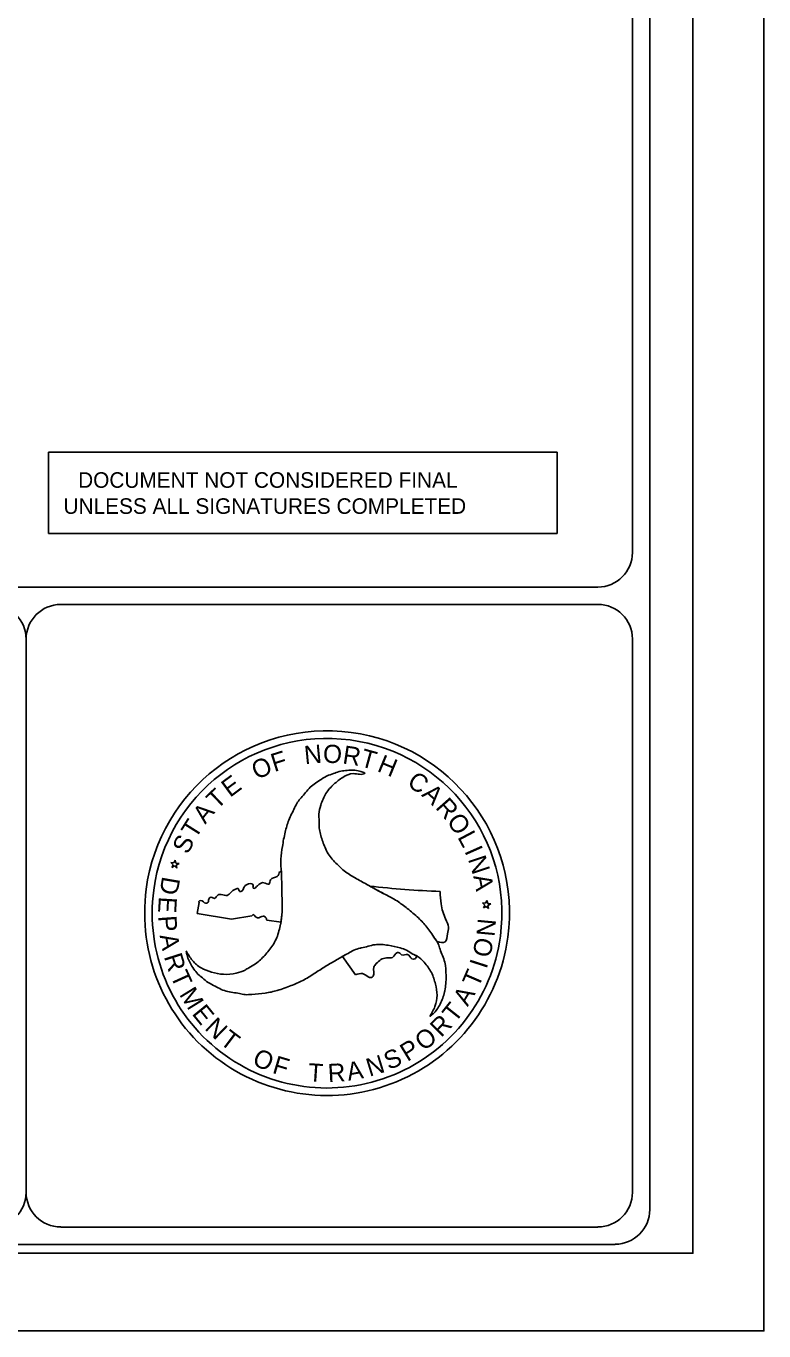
# Model space of a CAD drawing. Extents: x 2128934 to 2134034, y 641595 to 644895.
# Drawn here: x 2133394 to 2134034, y 641595 to 642727 of the extents above; entities that cross this region are included whole.
import ezdxf

# ---------------------------------------------------------------- set-up
doc = ezdxf.new("R2010")
doc.units = 0
for name, color, linetype in [('Sheet Plot Border Inside CELL', 7, 'Continuous'), ('Sheet Plot Border Outside CELL', 7, 'Continuous'), ('Sheet Sticker Exception Certification CELL', 7, 'Continuous'), ('Sheet Title CELL', 7, 'Continuous')]:
    doc.layers.add(name, color=color, linetype=linetype)

msp = doc.modelspace()

# ---------------------------------------------------------------- linework, layer by layer
at = {"layer": 'Sheet Plot Border Inside CELL'}
msp.add_lwpolyline([(2128972.8, 641662.5), (2133972.3, 641662.5), (2133972.3, 644827.8), (2128972.8, 644827.8)], close=True, dxfattribs=at)
at = {"layer": 'Sheet Plot Border Outside CELL'}
msp.add_lwpolyline([(2128933.8, 641595.1), (2134033.8, 641595.1), (2134033.8, 644895.1), (2128933.8, 644895.1)], close=True, dxfattribs=at)
at = {"layer": 'Sheet Sticker Exception Certification CELL'}
for p, q in [((2133413.5, 642286.9), (2133413.5, 642357.4)), ((2133413.5, 642357.4), (2133854.5, 642357.4)), ((2133854.5, 642357.4), (2133854.5, 642286.9)), ((2133854.5, 642286.9), (2133413.5, 642286.9))]:
    msp.add_line(p, q, dxfattribs=at)
at = {"layer": 'Sheet Title CELL'}
for p, q in [((2129629.8, 642240.2), (2133889.8, 642240.2)), ((2133424.1, 642225.2), (2133889.8, 642225.2)), ((2133394.1, 641715.2), (2133394.1, 642195.2)), ((2133688.1, 642079.3), (2133687.8, 642079)), ((2133688.1, 642079.3), (2133687.8, 642079)), ((2133521.5, 641999.5), (2133519.6, 642001.5)), ((2133519.6, 642001.5), (2133522.3, 642001.1)), ((2133520.4, 641997), (2133521.5, 641999.5)), ((2133522.7, 641998.4), (2133520.4, 641997)), ((2133522.3, 642001.1), (2133523.4, 642003.5)), ((2133524.7, 641996.5), (2133522.7, 641998.4)), ((2133523.4, 642003.5), (2133524, 642000.9)), ((2133524, 642000.9), (2133526.7, 642000.5)), ((2133526.7, 642000.5), (2133524.2, 641999.2)), ((2133524.2, 641999.2), (2133524.7, 641996.5)), ((2133692.1, 641980.8), (2133692.1, 641980.8)), ((2133542.5, 641957.3), (2133544.1, 641966.7)), ((2133792.5, 641966), (2133789.8, 641966.4)), ((2133789.8, 641966.4), (2133791.8, 641964.5)), ((2133791.8, 641964.5), (2133790.7, 641962)), ((2133790.7, 641962), (2133793, 641963.3)), ((2133793.7, 641968.4), (2133792.5, 641966)), ((2133793, 641963.3), (2133795, 641961.5)), ((2133794.3, 641965.8), (2133793.7, 641968.4)), ((2133796.9, 641965.6), (2133794.3, 641965.8)), ((2133794.5, 641964.2), (2133796.9, 641965.6)), ((2133795, 641961.5), (2133794.5, 641964.2)), ((2133572.1, 641952.2), (2133542.5, 641957.3)), ((2133589.9, 641955), (2133572.1, 641952.2)), ((2133615.1, 641949.5), (2133602.7, 641951.3)), ((2133811.7, 641936.5), (2133811.7, 641936.5)), ((2133679.6, 641903.9), (2133668.3, 641919.9)), ((2133668.3, 641919.9), (2133668.3, 641919.9))]:
    msp.add_line(p, q, dxfattribs=at)
for points in [[(2133934.8, 641700.2), (2133934.8, 644790.1)], [(2133919.8, 642270.1), (2133919.8, 644775.2)], [(2133919.8, 641715.2), (2133919.8, 642195.2)], [(2133424.1, 641685.2), (2133889.8, 641685.2)], [(2129464.8, 641670.1), (2133904.8, 641670.1)]]:
    msp.add_lwpolyline(points, dxfattribs=at)
for centre, radius, start, end in [((2133889.8, 642270.3), 30, 270, 360), ((2133364.1, 642195.2), 30, 0, 90), ((2133424.1, 642195.2), 30, 90, 180), ((2133889.8, 642195.3), 30, 0, 90), ((2133655, 641957.4), 158.2, 352.4211, 172.4211), ((2133655, 641957.4), 151.6, 352.4211, 172.4211), ((2133785.9, 642809.4), 833.8, 258.0996, 258.1992), ((2133655, 641957.4), 158.1, 172.4211, 352.4211), ((2133655, 641957.4), 151.6, 172.4211, 352.4211), ((2133785.9, 642809.4), 833.8, 263.5387, 267.7447), ((2133364.1, 641715.3), 30, 270, 360), ((2133424.1, 641715.3), 30, 180, 270), ((2133889.8, 641715.3), 30, 270, 360), ((2133904.8, 641700.3), 30, 270, 360)]:
    msp.add_arc(centre, radius, start, end, dxfattribs=at)
for points in [[(2133687.8, 642079), (2133684.4, 642080.4), (2133673.9, 642081.4), (2133662.9, 642079.4), (2133661.9, 642079), (2133656.2, 642077), (2133650, 642073.5), (2133640.5, 642066.6), (2133632.6, 642057.6), (2133629.5, 642053.7), (2133626.9, 642048.8), (2133621.9, 642038.2), (2133618.7, 642027.7), (2133616.3, 642015.3), (2133615, 642004.3), (2133615.4, 641992.9), (2133615.8, 641981.3), (2133616, 641970.1), (2133616, 641958.7), (2133614.6, 641947.4), (2133614.4, 641946.5), (2133610.8, 641934.8), (2133604.6, 641925), (2133597.2, 641917), (2133593, 641913.5), (2133587.2, 641910.1), (2133583.9, 641908.1), (2133576.3, 641905.4), (2133565.2, 641904.4), (2133554.8, 641906.4), (2133545.8, 641910), (2133538.4, 641916.3), (2133532.9, 641924.7)], [(2133744.1, 641867.8), (2133746.9, 641870), (2133753, 641878.6), (2133756.9, 641889.1), (2133757.1, 641890.2), (2133758, 641896.2), (2133758.2, 641903.3), (2133757.1, 641915), (2133753, 641926.2), (2133751.4, 641930.9), (2133748.3, 641935.8), (2133741.6, 641945.3), (2133734.2, 641953.3), (2133724.6, 641961.5), (2133715.7, 641968), (2133705.6, 641973.6), (2133695.5, 641979), (2133685.8, 641984.4), (2133675.6, 641990.2), (2133666.7, 641997), (2133666, 641997.7), (2133657.6, 642006.6), (2133652.2, 642017), (2133649, 642027.3), (2133648.2, 642032.6), (2133648.1, 642039.4), (2133647.9, 642043.3), (2133649.6, 642051.1), (2133654.1, 642061.3), (2133661, 642069.3), (2133668.6, 642075.2), (2133677.9, 642078.5), (2133687.8, 642079), (2133688.1, 642079.3)], [(2133544.1, 641966.7), (2133543.9, 641967.6), (2133545.6, 641968.4), (2133549.8, 641966), (2133552.3, 641967.6), (2133552.4, 641969.6), (2133554.5, 641971.2), (2133557.4, 641970.2), (2133560.6, 641973.4), (2133563.2, 641973.6), (2133568.5, 641972.9), (2133575.6, 641978.4), (2133578.3, 641978.4), (2133578.7, 641976.7), (2133580.3, 641976.1), (2133583.7, 641981), (2133584.5, 641981.6), (2133589.7, 641982.9), (2133590.9, 641981.8), (2133590.9, 641979.4), (2133591.6, 641978.9), (2133593.3, 641979.8), (2133595.9, 641982.3), (2133600.2, 641983.9), (2133604.7, 641982.7), (2133606, 641986.4), (2133611.9, 641989.3), (2133613.3, 641991.3), (2133613.9, 641993.5)], [(2133615.4, 641993.2), (2133615.4, 641992.9), (2133615.8, 641981.3), (2133616, 641970.1), (2133616, 641958.7), (2133615, 641949.5)], [(2133750.4, 641932.8), (2133748.3, 641935.8), (2133741.6, 641945.3), (2133734.2, 641953.3), (2133724.6, 641961.5), (2133715.7, 641968), (2133705.6, 641973.6), (2133695.5, 641979), (2133692.1, 641980.8)], [(2133753.1, 641976.2), (2133753.9, 641965.4), (2133757.8, 641952.4), (2133760.4, 641945.2), (2133759.5, 641939.4), (2133757.3, 641932.6), (2133750.5, 641932.8)], [(2133602.7, 641951.3), (2133601.8, 641953.7), (2133599.5, 641954.8), (2133596, 641953.5), (2133593.5, 641953.9), (2133591.1, 641956.2), (2133589.9, 641955)], [(2133532.9, 641924.7), (2133533.6, 641921), (2133537.9, 641911.4), (2133545.1, 641902.8), (2133545.9, 641902.2), (2133550.6, 641898.3), (2133556.7, 641894.7), (2133567.5, 641889.8), (2133579.1, 641887.7), (2133584, 641886.8), (2133589.9, 641887), (2133601.3, 641888.1), (2133611.9, 641890.4), (2133623.9, 641894.6), (2133633.9, 641899), (2133643.8, 641905), (2133653.5, 641911.2), (2133663.2, 641916.9), (2133673.2, 641922.6), (2133683.6, 641927.1), (2133684.7, 641927.3), (2133696.6, 641930.1), (2133708.1, 641929.6), (2133718.5, 641927.3), (2133723.9, 641925.4), (2133729.5, 641921.9), (2133733.1, 641920.2), (2133739.1, 641914.9), (2133745.5, 641905.9), (2133749, 641895.9), (2133750.4, 641886.3), (2133748.6, 641876.6), (2133744.1, 641867.8)], [(2133668.3, 641919.9), (2133673.2, 641922.6), (2133683.6, 641927.1), (2133684.7, 641927.3), (2133696.6, 641930.1), (2133708.1, 641929.6), (2133718.5, 641927.3), (2133723.9, 641925.4), (2133729.5, 641921.9), (2133732.9, 641920.3)], [(2133732.8, 641920.2), (2133731, 641917.7), (2133728.6, 641917.8), (2133724.9, 641921.7), (2133719.7, 641921.3), (2133717.6, 641923), (2133716, 641923.2), (2133711.8, 641919.1), (2133706.6, 641918.7), (2133697.7, 641913.7), (2133695.5, 641910.5), (2133695.1, 641902.9), (2133692.9, 641901.6), (2133690.6, 641902.3), (2133685.8, 641905), (2133679.6, 641903.9)]]:
    msp.add_spline(points, degree=3, dxfattribs=at)

# ---------------------------------------------------------------- texts
at = {"layer": 'Sheet Sticker Exception Certification CELL'}
for s, p in [('DOCUMENT NOT CONSIDERED FINAL', (2133439.2, 642326.4)), ('UNLESS ALL SIGNATURES COMPLETED', (2133426.5, 642303.8))]:
    msp.add_text(s, height=13.5, dxfattribs=at).set_placement(p)
at = {"layer": 'Sheet Title CELL'}
for s, height, rotation, p in [('N', 15.8, 5.4049, (2133635.9, 642086.6)), ('O', 15.8, 357.9068, (2133651.3, 642088)), ('R', 15.8, 351.2969, (2133667.9, 642087.4)), ('T', 15.8, 344.6472, (2133682.9, 642085.1)), ('O', 15.8, 24.6387, (2133594.1, 642072.9)), ('F', 15.8, 17.4918, (2133609.3, 642079.8)), ('H', 15.7, 337.5625, (2133697.7, 642080.9)), ('E', 15.7, 36.5781, (2133570.9, 642057.4)), ('C', 15.7, 325.2202, (2133723.5, 642068.7)), ('T', 15.7, 43.6937, (2133559.7, 642046.8)), ('A', 15.8, 317.7231, (2133736.4, 642059.6)), ('R', 15.8, 311.3592, (2133748.4, 642048.8)), ('A', 15.8, 50.7489, (2133549.4, 642034.1)), ('O', 15.8, 304.2396, (2133758.3, 642037.4)), ('T', 15.8, 57.8012, (2133541, 642021.2)), ('S', 15.8, 64.1774, (2133534.4, 642007.7)), ('L', 15.7, 298.0059, (2133767.8, 642023.5)), ('I', 15.8, 294.0166, (2133773.9, 642011.4)), ('N', 15.8, 288.3165, (2133777, 642004.3)), ('D', 15.8, 260.2741, (2133512.2, 641989.9)), ('A', 15.8, 280.8845, (2133781.7, 641989.6)), ('E', 15.7, 266.562, (2133509.3, 641972)), ('P', 15.8, 274.0944, (2133508.6, 641954.9)), ('N', 15.8, 84.6293, (2133800.2, 641936.7)), ('A', 15.7, 280.687, (2133509.8, 641938.1)), ('O', 15.7, 77.3812, (2133796.2, 641918.1)), ('R', 15.8, 287.7556, (2133513.4, 641919.8)), ('T', 15.8, 294.4062, (2133518.9, 641903.2)), ('T', 15.7, 66.5957, (2133786.2, 641892.1)), ('I', 15.8, 72.2456, (2133793.2, 641908.5)), ('M', 15.7, 301.6412, (2133526.5, 641887)), ('A', 15.8, 59.5113, (2133776.9, 641875.9)), ('E', 15.7, 309.108, (2133537.3, 641870.1)), ('T', 15.7, 51.4242, (2133766, 641861.7)), ('N', 15.8, 316.0795, (2133548.2, 641857.1)), ('R', 15.8, 45.3245, (2133753.9, 641849.1)), ('T', 15.7, 322.9215, (2133561.2, 641844.8)), ('O', 15.8, 38.1354, (2133738.9, 641837.3)), ('O', 15.8, 336.2252, (2133589.3, 641826.4)), ('S', 15.7, 24.2515, (2133708.7, 641821.1)), ('P', 15.8, 31.4434, (2133724.6, 641828.3)), ('F', 15.8, 343.3904, (2133606.8, 641819)), ('T', 15.7, 356.2997, (2133638.3, 641811.7)), ('R', 15.8, 3.2563, (2133656.1, 641810.8)), ('A', 15.7, 10.0094, (2133673.5, 641812)), ('N', 15.7, 17.041, (2133691.8, 641815.5))]:
    msp.add_text(s, height=height, rotation=rotation, dxfattribs=at).set_placement(p)

doc.saveas('drawing.dxf')
